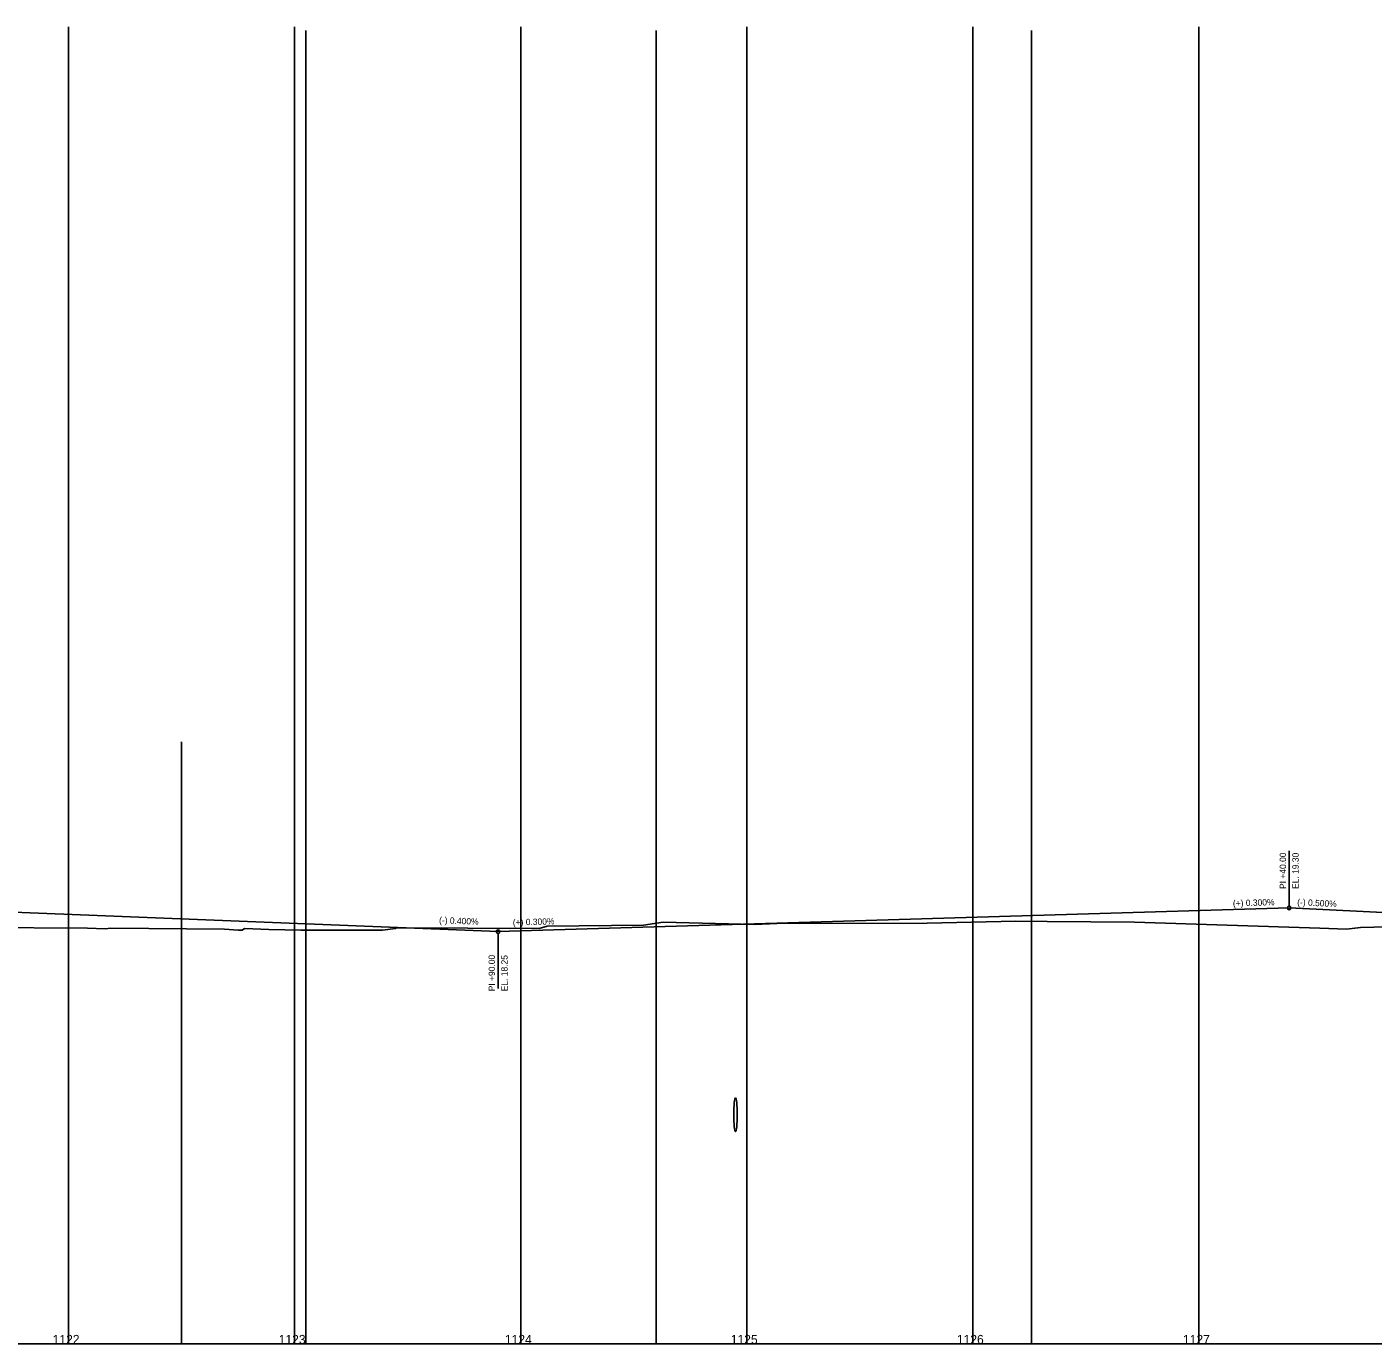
# Model space of a CAD drawing. Extents: x 1409 to 6106, y -2180 to -1584.
# Drawn here: x 1992 to 2588, y -2180 to -1597 of the extents above; entities that cross this region are included whole.
import ezdxf

# ---------------------------------------------------------------- set-up
doc = ezdxf.new("R2010")
doc.units = 0
for name, color, linetype in [('CLConst_dp', 7, 'Continuous'), ('LaneLine', 7, 'Continuous'), ('Miscellaneous0', 7, 'Continuous'), ('NonPlottingEle_dp', 7, 'Continuous'), ('Pedestal_ep', 7, 'Continuous'), ('PipeCulvert_ep', 7, 'Continuous'), ('StationTicS_dp', 7, 'Continuous'), ('TextLabel', 7, 'Continuous'), ('TextProfLabel', 7, 'Continuous'), ('TextPtLabel', 7, 'Continuous')]:
    doc.layers.add(name, color=color, linetype=linetype)

msp = doc.modelspace()

# ---------------------------------------------------------------- linework, layer by layer
at = {"layer": 'CLConst_dp'}
msp.add_line((1410.73, -2179.71), (6032.47, -2179.71), dxfattribs=at)
at = {"layer": 'Miscellaneous0'}
for p, q in [((2010.73, -2179.71), (2010.73, -1596.74)), ((2110.73, -2179.71), (2110.73, -1596.74)), ((2210.73, -2179.71), (2210.73, -1596.74)), ((2310.73, -2179.71), (2310.73, -1596.74)), ((2410.73, -2179.71), (2410.73, -1596.74)), ((2510.73, -2179.71), (2510.73, -1596.74))]:
    msp.add_line(p, q, dxfattribs=at)
at = {"layer": 'NonPlottingEle_dp'}
for p, q in [((2550.73, -1985.91), (2550.73, -1961.51)), ((2200.73, -1998.01), (2200.73, -2022.41))]:
    msp.add_line(p, q, dxfattribs=at)
for centre in [(2550.73, -1986.71), (2200.73, -1997.21)]:
    msp.add_circle(centre, 0.8, dxfattribs=at)
at = {"layer": 'Pedestal_ep'}
msp.add_line((2060.73, -2179.71), (2060.73, -1913.26), dxfattribs=at)
at = {"layer": 'PipeCulvert_ep'}
msp.add_ellipse((2305.78, -2078.21), major_axis=(0, 7.5), ratio=0.1, dxfattribs=at)
at = {"layer": 'StationTicS_dp'}
msp.add_lwpolyline([(1924.29, -1995.09), (2019.13, -1995.61), (2026.9, -1996.03), (2029.38, -1995.72), (2079.62, -1996.18), (2085.8, -1996.6), (2086.87, -1996.61), (2087.48, -1996.51), (2088.55, -1995.79), (2092.3, -1996.02), (2099.26, -1996.29), (2113.49, -1996.58), (2146.18, -1996.62), (2149.62, -1996.55), (2155.31, -1995.83), (2155.85, -1995.47), (2218.88, -1995.82), (2222.42, -1994.77), (2265.03, -1994.3), (2273.77, -1993.08), (2314.12, -1993.97), (2324, -1993.62), (2390.57, -1993.49), (2429.81, -1992.54), (2443.63, -1992.65), (2482.36, -1993.02), (2564.25, -1995.69), (2576.04, -1996.06), (2582.27, -1995.38), (2671.02, -1993.11)], dxfattribs=at)
msp.add_lwpolyline([(1924.29, -1995.09), (2019.13, -1995.61), (2026.9, -1996.03), (2029.38, -1995.72), (2079.62, -1996.18), (2085.8, -1996.6), (2086.87, -1996.61), (2087.48, -1996.51), (2088.55, -1995.79), (2092.3, -1996.02), (2099.26, -1996.29), (2113.49, -1996.58), (2146.18, -1996.62), (2149.62, -1996.55), (2155.31, -1995.83), (2155.85, -1995.47), (2218.88, -1995.82), (2222.42, -1994.77), (2265.03, -1994.3), (2273.77, -1993.08), (2314.12, -1993.97), (2324, -1993.62), (2390.57, -1993.49), (2429.81, -1992.54), (2443.63, -1992.65), (2482.36, -1993.02), (2564.25, -1995.69), (2576.04, -1996.06), (2582.27, -1995.38), (2671.02, -1993.11)], dxfattribs=at)
at = {"layer": 'TextLabel'}
for p, q in [((2115.73, -2179.71), (2115.73, -1598.37)), ((2270.73, -2179.71), (2270.73, -1598.37)), ((2436.73, -2179.71), (2436.73, -1598.37))]:
    msp.add_line(p, q, dxfattribs=at)
at = {"layer": 'TextPtLabel'}
for p, q in [((1940.73, -1986.81), (2200.73, -1997.21)), ((2200.73, -1997.21), (2550.73, -1986.71)), ((2550.73, -1986.71), (2850.73, -2001.71))]:
    msp.add_line(p, q, dxfattribs=at)

# ---------------------------------------------------------------- texts
at = {"layer": 'LaneLine'}
for s, rotation, p in [('(+) 0.300%', 1.71836, (2525.86, -1986.06)), ('(-) 0.500%', 357.13759, (2554.23, -1985.49)), ('(-) 0.400%', 357.70939, (2174.58, -1993.48)), ('(+) 0.300%', 1.71836, (2207.29, -1994.53))]:
    msp.add_text(s, height=2.8, rotation=rotation, dxfattribs=at).set_placement(p)
at = {"layer": 'NonPlottingEle_dp'}
for s, p in [('PI +40.00', (2549.33, -1978.31)), ('EL. 19.30', (2554.93, -1978.31)), ('PI +90.00', (2199.33, -2023.61)), ('EL. 18.25', (2204.93, -2023.61))]:
    msp.add_text(s, height=2.8, rotation=90, dxfattribs=at).set_placement(p)
at = {"layer": 'TextProfLabel'}
for s, p in [('1122', (2003.66, -2179.71)), ('1123', (2103.66, -2179.71)), ('1124', (2203.74, -2179.71)), ('1125', (2303.68, -2179.71)), ('1126', (2403.71, -2179.71)), ('1127', (2503.75, -2179.71))]:
    msp.add_text(s, height=4, dxfattribs=at).set_placement(p)

doc.saveas('drawing.dxf')
